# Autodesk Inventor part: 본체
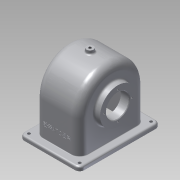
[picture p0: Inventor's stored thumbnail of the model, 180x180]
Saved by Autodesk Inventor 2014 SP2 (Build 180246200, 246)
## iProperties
Created: 2016-01
Part Number: 본체
Material: 알루미늄 6061
Document SubType Name: Modeling
Designer: Administrator
Density: 2.71 g/cm^3
Appearance: 알루미늄 - 평지
Mass: 770.52 g
Surface Area: 1007.17 cm^2
Volume: 284.325 cm^3
Author: Administrator
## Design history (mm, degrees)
sketch "스케치2"
  geometry: L1 (-52, 70)-(52, 70); L2 (52, 70)-(52, -70); L3 (52, -70)-(-52, -70); L4 (-52, -70)-(-52, 70); 1 further point
  constraints: 8 end point, 2 parallel, 1 horizontal, 1 perpendicular
  dimensions: "d6" = 104 distance of L2.end L3.end; "d7" = 140 distance of L3.end L1.start; "d8" = 52 distance from line of L4 point (0, 0) (= 0.5 x d6); "d9" = 70 distance from line of L3 point (0, 0) (= 0.5 x d7)
extrude "돌출2" new body sketch "스케치2" distance "d10" = 7; taper "d11" = 0 deg
node "작업 평면1"
sketch "스케치3"
  geometry: L1 (-70, 0)-(70, 0) reference; L2 (-70, 0)-(-70, 7) reference; L3 (70, 7)-(-70, 7) reference; L4 (70, 0)-(70, 7) reference; L5 (-57, 64)-(-57, 7); L6 (57, 64)-(57, 7); L7 (-57, 7)-(57, 7); A1 r 57 centre (0, 64) between (57, 64) and (-57, 64); 2 further points
  constraints: 6 end point, 2 perpendicular, 2 point on circle, 2 point on line, 2 tangent, 1 centre point, 1 collinear, 1 midpoint, 1 vertical alignment
  dimensions: "d15" = 64 distance from line of L1 A1.centre
extrude "돌출3" join sketch "스케치3" distance "d16" = 77; taper "d17" = 0 deg
node "작업 평면2"
sketch "스케치4"
  geometry: L1 (-7, -57)-(-7, 57) reference; L2 (-7, -57)-(-64, -57) reference; L3 (-64, 57)-(-7, 57) reference; L4 (-64, -51)-(0, -51); L5 (0, 51)-(-64, 51); L6 (0, -70)-(0, 70) reference; A1 r 57 centre (-64, 0) between (-64, 57) and (-64, -57) reference; A2 r 51 centre (-64, 0) between (-64, 51) and (-64, -51); 1 further point
  constraints: 4 end point, 2 point on circle, 2 point on line, 1 centre point
  dimensions: "d95" = 6 radial gap between concentric circles of A2 A1
extrude "돌출4" cut sketch "스케치4" distance "d20" = 67; taper "d21" = 0 deg
sketch "스케치7"
  geometry: C1 r 31 at (-64, 0); A1 r 57 centre (-64, 0) between (-64, 57) and (-64, -57) reference; 1 further point
  constraints: 1 centre point, 1 coincident
  dimensions: "d22" = 62 diameter of C1
extrude "돌출5" join sketch "스케치7" distance "d23" = 10; taper "d24" = 0 deg
sketch "스케치8"
  geometry: C1 r 31 at (0, 0) reference; C2 r 20 at (0, 0); 1 further point
  constraints: 1 centre point, 1 coincident
  dimensions: "d25" = 40 diameter of C2
extrude "돌출6" cut sketch "스케치8" distance "d26" = 15; taper "d27" = 0 deg
chamfer "모따기1" distance "d28" = 1; stored, may be unused: second distance "d29" = 2, angle "d30" = 45 deg
sketch "스케치9"
  geometry: L1 (-48.5, 85)-(-48.5, 43) reference; L2 (38.5, 64)-(38.5, 121) reference; L3 (-38.5, 121)-(-38.5, 64) reference; L4 (-38.5, 121)-(38.5, 121) reference; L5 (33.5, 103.747)-(33.5, 64) reference; L6 (19.5, 92)-(19.5, 64); L7 (33.5, 103.747)-(19.5, 92); L8 (-48.5, 64)-(33.5, 64) reference; 1 further point
  constraints: 8 end point, 1 horizontal, 1 midpoint, 1 perpendicular, 1 point on line, 1 vertical
  dimensions: "d34" = 50 deg angle of L7 L6; "d97" = 56 diameter of L6.start L8
revolve "회전1" sketch "스케치9" stored, may be unused: angle "d35" = 90 deg
sketch "스케치10"
  geometry: L1 (19.5, 36)-(19.5, 92) reference; L2 (33.5, 24.253)-(33.5, 103.747) reference; L3 (19.5, 92)-(33.5, 103.747) reference; L4 (35.5, 98.899)-(38.5, 101.416); L5 (-33.5, 64)-(-33.5, 0) reference; L6 (33.5, 0)-(-33.5, 0) reference; L7 (33.5, 0)-(33.5, 64) reference; L8 (-33.5, 64)-(33.5, 64) reference; L9 (38.5, 64)-(38.5, 121) reference; L10 (38.5, 7)-(38.5, 64) reference; L11 (38.5, 64)-(-52.757, 64); L12 (38.5, 101.416)-(38.5, 64); L13 (38.5, 64)-(35.5, 64); L14 (35.5, 98.899)-(35.5, 64); 3 further points
  constraints: 10 end point, 5 point on line, 2 collinear, 1 parallel, 1 perpendicular
  dimensions: "d36" = 5 distance between parallel lines of L3 L4; "d40" = 3 distance between parallel lines of L14 L12
  node "투영된 루프4"
  node "투영된 루프5"
node "작업 평면4"
revolve "회전3" stored, may be unused: angle "d41" = 90 deg
sketch "스케치12"
  geometry: C1 r 34.899 at (0, 0) reference; C2 r 20 at (0, 0); 1 further point
  constraints: 1 centre point, 1 coincident
  dimensions: "d42" = 40 diameter of C2
extrude "돌출7" cut sketch "스케치12" distance "d43" = 16; taper "d44" = 0 deg
chamfer "모따기2" distance "d45" = 1; stored, may be unused: second distance "d46" = 2, angle "d47" = 45 deg
sketch "스케치13"
  geometry: C1 r 21 at (0, 0) reference; A1 r 28 centre (0, 0) between (0, 28) and (28, 0); 3 further points
  constraints: 4 point on circle, 1 centre point, 1 coincident
  dimensions: "d48" = 56 diameter of A1
hole "구멍1" sketch "스케치13" at (0, 28), (28, 0), (0, -28), (-28, 0) diameter "d49" = 2.621; stored, may be unused: countersink angle "d53" = 90 deg, drill point angle "d55" = 118 deg; dims "d50" = 6, "d51" = 4, "d52" = 2, "d54" = 9
sketch "스케치14"
  geometry: C1 r 21 at (0, 0) reference; A1 r 24 centre (0, 0) between (0, 24) and (0, -24); 3 further points
  constraints: 4 point on circle, 1 centre point, 1 coincident
  dimensions: "d56" = 48 diameter of A1
hole "구멍2" sketch "스케치14" at (0, 24), (0, -24), (24, 0), (-24, 0) diameter "d57" = 2.621; stored, may be unused: countersink angle "d61" = 90 deg, drill point angle "d63" = 118 deg; dims "d58" = 6, "d59" = 4, "d60" = 2, "d62" = 8
node "작업 평면6"
  node "작업 평면5"
sketch "스케치15"
  geometry: C1 r 6 at (-38.5, 0); 1 further point
  constraints: 1 centre point, 1 coincident
  dimensions: "d65" = 12 diameter of C1
extrude "돌출8" join sketch "스케치15" stored distance "d66" = 12 (= d65); taper "d67" = 0 deg
hole "구멍3" diameter "d70" = 4.459; stored, may be unused: countersink angle "d74" = 90 deg, drill point angle "d76" = 118 deg; dims "d68" = 10, "d69" = 10, "d71" = 15, "d72" = 4, "d73" = 2, "d75" = 15
sketch "스케치16"
  geometry: C1 r 2.5 at (-44, 62); C2 r 2.5 at (44, 62); C3 r 2.5 at (44, -62); C4 r 2.5 at (-44, -62); 1 further point
  constraints: 4 centre point, 3 equal radius, 2 horizontal alignment, 2 vertical alignment
  dimensions: "d77" = 5 diameter of C1; "d78" = 88 distance of C1.centre C2.centre; "d79" = 44 horizontal distance of point (0, 0) C2.centre (= 0.5 x d78); "d80" = 124 distance of C3.centre C2.centre; "d81" = 62 vertical distance of point (0, 0) C2.centre (= 0.5 x d80)
extrude "돌출9" cut sketch "스케치16" stored distance "d82" = 16; taper "d83" = 0 deg
sketch "스케치17"
  geometry: L1 (13.5, -7)-(-90.5, -7) reference; 4 further points
  constraints: 2 midpoint, 1 vertical alignment, 1 other
  dimensions: "d84" = 30 distance from line of L1 point (-38.5, 23)
feature "엠보싱1" sketch "스케치17" dims "d6" = 104, "d7" = 140, "d8" = 52 (= 0.5 x d6), "d9" = 70 (= 0.5 x d7), "d85" = 0.5, "d86" = 0
fillet "모깎기2" dims "d88" = 8
fillet "모깎기3" dims "d89" = 14
fillet "모깎기4" dims "d90" = 9
fillet "모깎기5" dims "d91" = 1
fillet "모깎기6" dims "d92" = 3
fillet "모깎기7" dims "d93" = 3
fillet "모깎기8" dims "d94" = 3
node "솔리드2"
node "투영된 루프1"
node "투영된 루프2"
other parameters: "d12" = 38.5, "d18" = -5, "d64" = 6
